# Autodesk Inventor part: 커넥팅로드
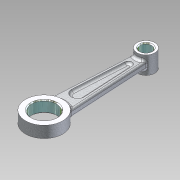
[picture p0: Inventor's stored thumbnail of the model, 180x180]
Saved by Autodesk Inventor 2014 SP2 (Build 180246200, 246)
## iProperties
Manager: KYOUNG IL JANG
Company: 한국ATC센터
Created: 2012-10
Part Number: 커넥팅로드
Document SubType Name: Modeling
Density: 1 g/cm^3
Checked By: KYOUNG IL JANG
Vendor: CBT Solutions
Designer: KYOUNG IL JANG
Material: 일반
Appearance: _시험_알루미늄 표면거칠기
Author: KYOUNG IL JANG
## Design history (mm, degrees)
sketch "스케치1"
  geometry: L1 (-19.879, 82.758)-(-19.879, 197.758); L2 (-27.379, 191.144)-(-32.379, 99.633); L3 (-12.379, 191.144)-(-7.379, 99.633); C1 r 14 at (-19.879, 82.758); C2 r 6.5 at (-19.879, 197.758); A1 r 19 centre (-19.879, 82.758) between (-20.11, 101.757) and (-19.649, 63.76) reference; A2 r 21 centre (-19.879, 82.758) between (-32.379, 99.633) and (-7.379, 99.633); A3 r 10 centre (-19.879, 197.758) between (-27.379, 191.144) and (-12.379, 191.144); 1 further point
  constraints: 6 end point, 4 centre point, 4 coincident, 4 point on circle, 2 horizontal alignment, 1 equal length, 1 vertical
  dimensions: "d0" = 28 diameter of C1; "d1" = 42 diameter of A2; "d4" = 115 distance of L1.end C1.centre; "d5" = 20 diameter of A3; "d6" = 13 diameter of C2; "d7" = 25 distance of L3.end L2.end; "d8" = 15 distance of L3.start L2.start
  node "참조1"
extrude "돌출1" new body sketch "스케치1" stored distance "d2" = 13; taper "d3" = 0 deg
extrude "돌출2" join sketch "스케치1" stored distance "d9" = 20; taper "d10" = 0 deg
extrude "돌출3" join sketch "스케치1" stored distance "d11" = 8; taper "d12" = 0 deg
sketch "스케치2"
  geometry: L1 (7.379, 99.633)-(12.379, 191.144) reference; L2 (27.379, 191.144)-(32.379, 99.633) reference; L3 (27.197, 121.158)-(24.092, 177.989); L4 (15.667, 177.989)-(12.561, 121.158); A1 r 21 centre (19.879, 82.758) between (7.379, 99.633) and (32.379, 99.633) reference; A2 r 7.329 centre (19.879, 120.758) between (12.561, 121.158) and (27.197, 121.158); A3 r 4.219 centre (19.879, 177.758) between (24.092, 177.989) and (15.667, 177.989); A4 r 10 centre (19.879, 197.758) between (12.379, 191.144) and (27.379, 191.144) reference; 2 further points
  constraints: 4 end point, 4 point on circle, 4 tangent, 2 centre point, 2 parallel, 1 coincident, 3 other
  dimensions: "d16" = 38 distance of A2.centre A1.centre; "d17" = 4 distance between parallel lines of L2 L3; "d18" = 4 distance between parallel lines of L4 L1; "d25" = 20 distance of A3.centre A4.centre
extrude "돌출4" cut sketch "스케치2" distance "d19" = 5; taper "d20" = 0 deg
fillet "모깎기1" dims "d21" = 2
fillet "모깎기2" dims "d22" = 3
fillet "모깎기3" dims "d23" = 3
chamfer "모따기1" distance "d26" = 1; stored, may be unused: second distance "d27" = 2, angle "d28" = 45 deg
chamfer "모따기2" distance "d29" = 1; stored, may be unused: second distance "d30" = 2, angle "d31" = 45 deg
node "솔리드1"
mirror "대칭1"
other parameters: "d13" = 5, "d14" = 5
